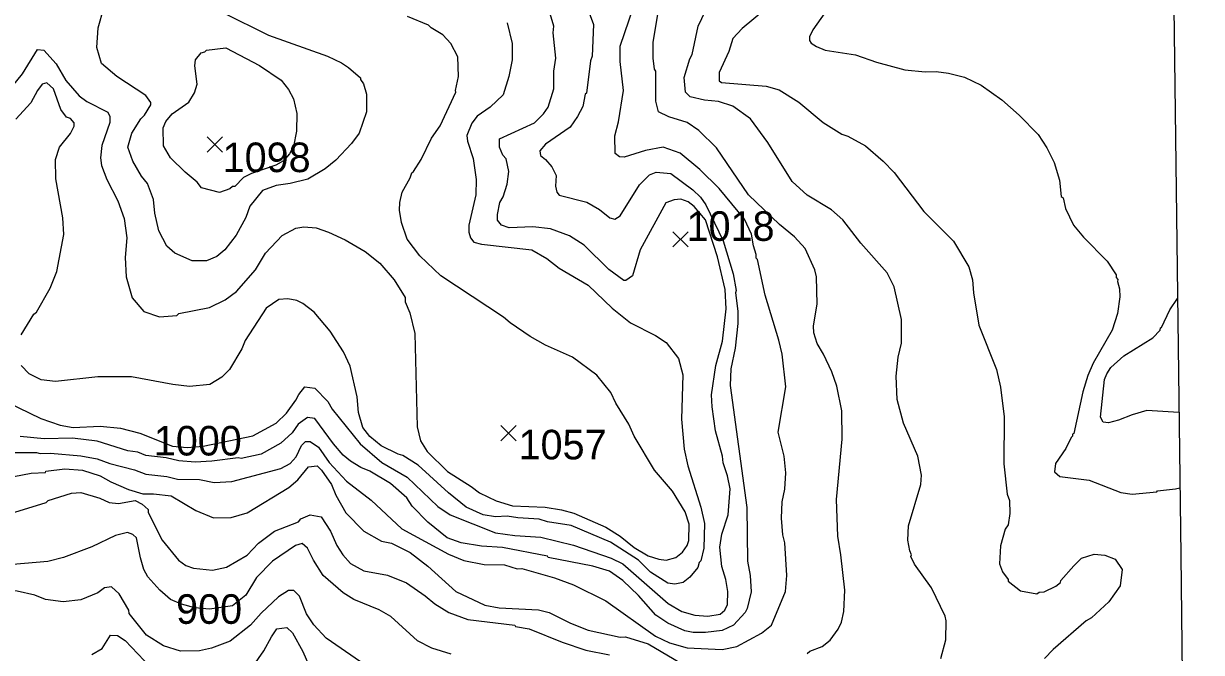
# Model space of a CAD drawing. Extents: x 265.7 to 292.1, y 7676.2 to 7704.2.
# Drawn here: x 288.719 to 291.905, y 7696.597 to 7698.298 of the extents above; entities that cross this region are included whole.
import ezdxf
from ezdxf.enums import TextEntityAlignment as Align

# ---------------------------------------------------------------- set-up
doc = ezdxf.new("R2010")
doc.units = 0
doc.header["$LTSCALE"] = 0.032
for name, color, linetype, lineweight in [('1', 7, 'Continuous', 25), ('2', 7, 'Continuous', 13), ('21', 7, 'Continuous', 25), ('63', 7, 'Continuous', 25)]:
    doc.layers.add(name, color=color, linetype=linetype, lineweight=lineweight)
doc.layers.add('61', color=7, linetype='Continuous')

msp = doc.modelspace()

# ---------------------------------------------------------------- linework, layer by layer
at = {"layer": '1'}
for points in [[(289.5532, 7697.2552), (289.629, 7697.1611), (289.688, 7697.1108), (289.7559, 7697.0709), (289.8396, 7696.9919), (289.8724, 7696.9696), (289.9953, 7696.9209), (290.0479, 7696.9129), (290.1181, 7696.9089), (290.2059, 7696.8874), (290.3081, 7696.8515), (290.34, 7696.8363), (290.4621, 7696.7294), (290.4996, 7696.7078), (290.5347, 7696.6975), (290.5698, 7696.6951), (290.6033, 7696.7006), (290.6153, 7696.711), (290.6224, 7696.727), (290.624, 7696.7621), (290.6185, 7696.794), (290.6073, 7696.8291), (290.6017, 7696.8818), (290.6073, 7696.9169), (290.6248, 7696.9696), (290.6296, 7697.0398), (290.6232, 7697.0749), (290.6113, 7697.11), (290.6097, 7697.1276), (290.5905, 7697.1962), (290.581, 7697.2616), (290.5794, 7697.2935), (290.5913, 7697.3733), (290.6089, 7697.4388), (290.6193, 7697.5265), (290.6161, 7697.5792), (290.5953, 7697.667), (290.563, 7697.7675), (290.5328, 7697.8033), (290.5163, 7697.8162), (290.4964, 7697.8234), (290.4788, 7697.821), (290.4557, 7697.813), (290.3862, 7697.6861), (290.3655, 7697.6159), (290.348, 7697.6031), (290.3424, 7697.6031), (290.3017, 7697.6327), (290.2354, 7697.6989), (290.1955, 7697.7236), (290.1437, 7697.7428), (290.0958, 7697.7484), (290.032, 7697.746), (290.0112, 7697.7532), (290.0008, 7697.7667), (290.0008, 7697.7819), (290.0072, 7697.8138), (290.016, 7697.8298), (290.0264, 7697.8633), (290.0312, 7697.8984), (290.024, 7697.9319), (290.0152, 7697.9423), (290.0056, 7697.9638), (290.0056, 7697.9862), (290.1006, 7698.0292), (290.1253, 7698.054), (290.1373, 7698.0724), (290.1532, 7698.1218), (290.1532, 7698.1697), (290.158, 7698.2048), (290.1516, 7698.2734), (290.1532, 7698.291), (290.1381, 7698.3421)], [(290.7254, 7698.3373), (290.6624, 7698.2846), (290.6368, 7698.2575), (290.6264, 7698.2224), (290.6001, 7698.1657), (290.6001, 7698.1434), (290.6065, 7698.1386), (290.7278, 7698.129), (290.7629, 7698.1186), (290.8156, 7698.0859), (290.8818, 7698.0301)], [(290.8818, 7698.0301), (290.9321, 7697.9989), (290.948, 7697.9933), (290.9959, 7697.967), (291.0438, 7697.9255), (291.0733, 7697.8952), (291.1539, 7697.7899)], [(291.1539, 7697.7899), (291.2345, 7697.7093), (291.2752, 7697.6399), (291.2856, 7697.6047), (291.2879, 7697.5696), (291.3023, 7697.4819), (291.3502, 7697.3622), (291.3614, 7697.3143), (291.3709, 7697.2345), (291.3701, 7697.1068), (291.3789, 7697.0254), (291.3853, 7697.0079), (291.3869, 7696.9728), (291.3821, 7696.9424), (291.3741, 7696.9305), (291.3614, 7696.885), (291.3582, 7696.8363), (291.3669, 7696.8148), (291.3821, 7696.794), (291.3821, 7696.79), (291.4156, 7696.7637), (291.4595, 7696.7557), (291.4659, 7696.7597), (291.4795, 7696.7613), (291.5114, 7696.7764), (291.5233, 7696.786), (291.5249, 7696.7916), (291.5593, 7696.8315), (291.5808, 7696.8515), (291.6151, 7696.8626), (291.6438, 7696.8602), (291.6718, 7696.8491), (291.6901, 7696.8212), (291.6853, 7696.7772), (291.6542, 7696.7342), (291.6079, 7696.6903), (291.5928, 7696.6823), (291.5034, 7696.6049), (291.4803, 7696.5809)], [(289.4295, 7697.2441), (289.455, 7697.2792), (289.463, 7697.2951), (289.4798, 7697.3151), (289.5069, 7697.3119), (289.5412, 7697.276), (289.5532, 7697.2552)], [(288.6419, 7697.2895), (288.7648, 7697.2297), (288.8175, 7697.2121), (288.8526, 7697.2058), (288.926, 7697.2089), (288.9803, 7697.2034), (289.0329, 7697.1898), (289.1217, 7697.155), (289.1613, 7697.1513), (289.2046, 7697.155), (289.3384, 7697.1833), (289.4016, 7697.2169), (289.4295, 7697.2441)], [(289.0872, 7696.7653), (289.0544, 7696.8012), (289.0441, 7696.8212), (289.0345, 7696.8531), (289.0241, 7696.9065), (289.0145, 7696.9161), (288.9994, 7696.9217), (288.9675, 7696.9129), (288.9036, 7696.8826), (288.827, 7696.8539), (288.784, 7696.8427), (288.6898, 7696.8347)], [(289.8756, 7696.5921), (289.8229, 7696.6089), (289.7846, 7696.628), (289.712, 7696.6943), (289.6801, 7696.7126), (289.6122, 7696.7405), (289.5827, 7696.7581), (289.5292, 7696.8052), (289.5029, 7696.8467), (289.4869, 7696.8786), (289.4718, 7696.8914), (289.4542, 7696.8858), (289.392, 7696.8435), (289.3489, 7696.7996), (289.3194, 7696.7517)], [(289.3194, 7696.7517), (289.2836, 7696.7233), (289.2214, 7696.7139), (289.1818, 7696.7177), (289.146, 7696.7271), (289.1159, 7696.7403), (289.0872, 7696.7653)]]:
    msp.add_lwpolyline(points, dxfattribs=at)
at = {"layer": '2'}
for points in [[(290.8379, 7696.5937), (290.8451, 7696.6001), (290.8786, 7696.6129), (290.9009, 7696.6304), (290.9225, 7696.66), (290.9313, 7696.6791), (290.9376, 7696.7078), (290.94, 7696.7653), (290.9297, 7696.861), (290.9209, 7696.9113), (290.9177, 7697.0111), (290.9329, 7697.1738), (290.9321, 7697.2505), (290.9185, 7697.3175), (290.9049, 7697.3558), (290.8826, 7697.4037), (290.865, 7697.4324), (290.8563, 7697.4611), (290.8555, 7697.4803), (290.865, 7697.5393), (290.8634, 7697.6127), (290.8586, 7697.6319), (290.8331, 7697.6893), (290.8044, 7697.7212), (290.7637, 7697.7548), (290.6799, 7697.8346), (290.5929, 7697.9622), (290.5451, 7698.0085), (290.5139, 7698.0301), (290.4645, 7698.046), (290.4365, 7698.0596), (290.4293, 7698.0883), (290.4293, 7698.1697), (290.4254, 7698.1745), (290.4214, 7698.2048), (290.4214, 7698.2479), (290.4453, 7698.3883)], [(291.2002, 7696.5802), (291.2137, 7696.6312), (291.2145, 7696.6823), (291.2113, 7696.6951), (291.1746, 7696.7717), (291.1284, 7696.8355), (291.1188, 7696.8563), (291.1204, 7696.861), (291.1156, 7696.8722), (291.1108, 7696.9009), (291.1124, 7696.9392), (291.1459, 7697.051), (291.1475, 7697.0765), (291.1379, 7697.1276), (291.0988, 7697.2169), (291.0821, 7697.2808), (291.0789, 7697.3446), (291.0845, 7697.3957), (291.0932, 7697.434), (291.0932, 7697.4978), (291.0741, 7697.5856), (291.0549, 7697.6239), (290.9839, 7697.7037), (290.9345, 7697.7675), (290.9041, 7697.7939), (290.8379, 7697.8338), (290.798, 7697.8713), (290.7318, 7697.9766), (290.6847, 7698.0404), (290.6368, 7698.0747), (290.5985, 7698.0875), (290.5602, 7698.0907), (290.5219, 7698.1003), (290.5091, 7698.113), (290.5059, 7698.1522), (290.5211, 7698.2032), (290.5275, 7698.2144), (290.5435, 7698.291), (290.5937, 7698.3971)], [(290.9081, 7698.358), (290.8539, 7698.2814), (290.8443, 7698.2623), (290.8443, 7698.2527), (290.8491, 7698.2455), (290.8634, 7698.2359), (290.8874, 7698.2264), (290.9688, 7698.2136), (291.0262, 7698.1936), (291.1028, 7698.1729), (291.1571, 7698.1673), (291.1874, 7698.1689), (291.2209, 7698.1641), (291.264, 7698.1529), (291.3087, 7698.1314)], [(288.1129, 7698.3165), (288.1153, 7698.2527), (288.1129, 7698.1761), (288.1177, 7698.0899), (288.1264, 7698.0396), (288.1328, 7698.0332), (288.1392, 7698.0005), (288.1671, 7697.9463), (288.2126, 7697.9048), (288.2876, 7697.8784), (288.3195, 7697.88), (288.4313, 7697.9231), (288.4759, 7697.9447), (288.515, 7697.971), (288.5717, 7698.0157), (288.6882, 7698.129), (288.7153, 7698.1625), (288.756, 7698.228), (288.7736, 7698.2264), (288.8071, 7698.1889), (288.8326, 7698.1442), (288.8685, 7698.1027), (288.8893, 7698.0875), (288.9467, 7698.0588)], [(289.2579, 7698.3285), (289.3808, 7698.267), (289.5404, 7698.2104), (289.5787, 7698.192), (289.5979, 7698.1793), (289.6298, 7698.1514), (289.6298, 7698.1466), (289.6378, 7698.1354), (289.6465, 7698.1075), (289.6465, 7698.0596), (289.6266, 7698.0021), (289.6058, 7697.9734), (289.5636, 7697.9287), (289.534, 7697.9056), (289.4878, 7697.8776), (289.4399, 7697.8657), (289.4016, 7697.8601), (289.3649, 7697.8465), (289.3306, 7697.8042), (289.3202, 7697.7739), (289.2938, 7697.726), (289.2627, 7697.6861), (289.2412, 7697.6678), (289.2133, 7697.6566), (289.175, 7697.6566), (289.1279, 7697.6766), (289.1063, 7697.6957), (289.0848, 7697.7372), (289.0736, 7697.7851), (289.0704, 7697.8226), (289.0537, 7697.8657), (289.0377, 7697.8856), (289.0138, 7697.9255), (289.0002, 7697.9638), (289.0114, 7698.0021), (289.0361, 7698.0404), (289.0457, 7698.05), (289.0624, 7698.0787), (289.0624, 7698.0843), (289.0497, 7698.1035), (288.9707, 7698.1553), (288.9292, 7698.1904), (288.9164, 7698.2335), (288.9204, 7698.2862), (288.9356, 7698.3405)], [(288.9435, 7697.8761), (288.9739, 7697.8186), (288.9906, 7697.7707), (288.9978, 7697.7181), (288.9938, 7697.6654), (288.9962, 7697.6127), (289.0122, 7697.5561), (289.0441, 7697.5194), (289.0864, 7697.505), (289.1327, 7697.5082), (289.139, 7697.5138), (289.2212, 7697.5305), (289.2643, 7697.5505), (289.2947, 7697.5736), (289.3457, 7697.6319), (289.3728, 7697.6766), (289.4183, 7697.7252), (289.455, 7697.7444), (289.4766, 7697.7484), (289.5101, 7697.7452), (289.5436, 7697.734), (289.5883, 7697.7133), (289.6426, 7697.6813), (289.6825, 7697.6502), (289.7215, 7697.6047), (289.7511, 7697.5569), (289.7511, 7697.5457), (289.7638, 7697.5154), (289.7766, 7697.4595), (289.783, 7697.2074), (289.7926, 7697.1691), (289.8101, 7697.1403), (289.8652, 7697.0861), (289.9298, 7697.0462), (289.9522, 7697.0286), (289.9969, 7697.0071), (290.0415, 7696.9935), (290.1293, 7696.9895), (290.174, 7696.9831), (290.2075, 7696.9736), (290.2937, 7696.936), (290.332, 7696.9113), (290.3703, 7696.881), (290.4086, 7696.8586), (290.4373, 7696.8491), (290.4565, 7696.8467), (290.4828, 7696.8539), (290.5012, 7696.8682), (290.5139, 7696.8858), (290.5179, 7696.8994), (290.5195, 7696.944), (290.5083, 7696.9776), (290.474, 7697.0334), (290.4254, 7697.0901), (290.3703, 7697.1818), (290.3559, 7697.2145), (290.3208, 7697.2712), (290.3073, 7697.2999), (290.269, 7697.347), (290.2035, 7697.3957), (290.1309, 7697.4284), (290.0894, 7697.4515), (290.0352, 7697.4882), (290.0168, 7697.5042), (289.8476, 7697.6159), (289.7902, 7697.6702), (289.7559, 7697.7149), (289.7407, 7697.7596), (289.7359, 7697.7931), (289.7367, 7697.8138), (289.7431, 7697.8425), (289.7646, 7697.8808), (289.7686, 7697.8944), (289.7734, 7697.8976), (289.7942, 7697.9303), (289.8221, 7697.9878), (289.8452, 7698.0213), (289.8883, 7698.113), (289.8867, 7698.117), (289.8947, 7698.1553), (289.8931, 7698.208), (289.8748, 7698.2447), (289.8524, 7698.2679), (289.8213, 7698.2862), (289.8141, 7698.2934), (289.7575, 7698.3173)], [(290.0192, 7696.8339), (290.0535, 7696.8235), (290.0663, 7696.8243), (290.1548, 7696.7988), (290.2059, 7696.7796), (290.2937, 7696.7366), (290.4278, 7696.6408), (290.4661, 7696.6225), (290.5139, 7696.6097), (290.6081, 7696.6049), (290.648, 7696.6129), (290.715, 7696.6488), (290.7421, 7696.6711), (290.7797, 7696.7621), (290.7836, 7696.8052), (290.7781, 7696.893), (290.7725, 7696.9153), (290.7693, 7696.96), (290.7709, 7697.0047), (290.7781, 7697.0382), (290.7804, 7697.0829), (290.7765, 7697.1276), (290.7597, 7697.193), (290.7805, 7697.3151), (290.7709, 7697.4037), (290.7621, 7697.442), (290.7246, 7697.5633), (290.7038, 7697.6598), (290.7007, 7697.6638), (290.7007, 7697.6734), (290.6927, 7697.6973), (290.6879, 7697.7281), (290.6691, 7697.769), (290.6001, 7697.8521), (290.5482, 7697.9032), (290.4948, 7697.9479), (290.4485, 7697.9638), (290.4006, 7697.955), (290.3432, 7697.9367), (290.3304, 7697.9375), (290.3192, 7697.9471), (290.3176, 7697.9949), (290.328, 7698.0325), (290.3416, 7698.117), (290.3328, 7698.1952), (290.3328, 7698.2367), (290.3687, 7698.3421)], [(290.2458, 7698.3341), (290.2602, 7698.2958), (290.257, 7698.2096), (290.2522, 7698.1976), (290.241, 7698.1099), (290.2378, 7698.1075), (290.2314, 7698.0739), (290.2171, 7698.0468), (290.1971, 7698.0181), (290.1309, 7697.9718), (290.115, 7697.9542), (290.1165, 7697.9415), (290.1309, 7697.9303), (290.1477, 7697.9104), (290.1596, 7697.8872), (290.1572, 7697.8585), (290.1612, 7697.8417), (290.1676, 7697.8338), (290.2426, 7697.8146), (290.2761, 7697.7955), (290.3049, 7697.7723), (290.3184, 7697.7691), (290.3328, 7697.7779), (290.3847, 7697.8617), (290.4118, 7697.8888), (290.4301, 7697.896), (290.4693, 7697.8928), (290.5291, 7697.8481), (290.5498, 7697.8282)], [(290.0272, 7698.3006), (290.0399, 7698.2447), (290.0407, 7698.2), (290.0312, 7698.1553), (290.016, 7698.1051), (289.9809, 7698.0723), (289.9458, 7698.0476), (289.9314, 7698.0285), (289.9179, 7697.9957), (289.9194, 7697.9798), (289.9346, 7697.9335), (289.9426, 7697.8761), (289.9418, 7697.8346), (289.9234, 7697.7532), (289.9234, 7697.734)], [(288.7121, 7697.4563), (288.7464, 7697.5122), (288.7536, 7697.517), (288.7903, 7697.5824), (288.8087, 7697.6271), (288.8278, 7697.7276), (288.8246, 7697.7723), (288.8055, 7697.8777), (288.8047, 7697.9303), (288.8159, 7697.9638), (288.8454, 7698.0005), (288.8558, 7698.0205), (288.8558, 7698.0293), (288.8454, 7698.0412), (288.835, 7698.0452), (288.8191, 7698.066), (288.7991, 7698.1218), (288.7816, 7698.1378), (288.7688, 7698.1346), (288.756, 7698.117), (288.7385, 7698.0835), (288.6978, 7698.0396)], [(291.3087, 7698.1314), (291.3646, 7698.0923), (291.4116, 7698.0508), (291.4635, 7697.9981), (291.4866, 7697.9622), (291.5066, 7697.9223), (291.521, 7697.8745)], [(288.9467, 7698.0588), (288.9515, 7698.0468), (288.9515, 7698.0301), (288.93, 7697.9686), (288.9268, 7697.9351), (288.9292, 7697.9144), (288.9435, 7697.8761)], [(291.521, 7697.8745), (291.5257, 7697.8306), (291.5305, 7697.8266), (291.5369, 7697.7979), (291.5585, 7697.7532), (291.5856, 7697.7205), (291.6502, 7697.6558), (291.6742, 7697.6183), (291.6742, 7697.6111), (291.679, 7697.6055), (291.6774, 7697.6), (291.6829, 7697.5808), (291.6845, 7697.5585), (291.6782, 7697.5138), (291.663, 7697.4691), (291.6119, 7697.3797), (291.5976, 7697.3462), (291.584, 7697.3015), (291.5593, 7697.189), (291.5561, 7697.1874), (291.5561, 7697.1818), (291.5521, 7697.1786), (291.5385, 7697.1483), (291.5098, 7697.1076), (291.5074, 7697.0853), (291.5218, 7697.0725), (291.6008, 7697.0629), (291.6869, 7697.0294), (291.7173, 7697.0254), (291.7843, 7697.031), (291.7859, 7697.0342), (291.8346, 7697.0398), (291.8465, 7697.0423)], [(290.5498, 7697.8282), (290.5642, 7697.8074), (290.6115, 7697.7106), (290.6384, 7697.6207), (290.6464, 7697.576), (290.6448, 7697.5696), (290.6504, 7697.5202)], [(289.9234, 7697.734), (289.9274, 7697.7189), (289.937, 7697.7069), (289.957, 7697.7013), (290.0934, 7697.6861), (290.1341, 7697.663), (290.1676, 7697.6367)], [(290.1676, 7697.6367), (290.2458, 7697.5904), (290.3112, 7697.5281), (290.3607, 7697.489), (290.4278, 7697.4547), (290.4565, 7697.4356), (290.49, 7697.3925), (290.502, 7697.3478), (290.498, 7697.2281), (290.5059, 7697.1467), (290.5155, 7697.102), (290.5506, 7696.9903), (290.5602, 7696.9456), (290.5586, 7696.8786), (290.5506, 7696.8451), (290.5458, 7696.8403), (290.5427, 7696.8267), (290.5211, 7696.8004), (290.5028, 7696.786), (290.4804, 7696.7812), (290.4613, 7696.7844), (290.4142, 7696.814), (290.3823, 7696.8467), (290.3065, 7696.8954), (290.1995, 7696.94), (290.1357, 7696.9504), (290.1134, 7696.9576), (290.0559, 7696.9608), (290.0272, 7696.9656), (289.9953, 7696.964), (289.9617, 7696.9688), (289.9155, 7696.9903), (289.8684, 7697.0286), (289.7862, 7697.1036), (289.7447, 7697.13), (289.7319, 7697.1331), (289.6857, 7697.1555), (289.6553, 7697.181), (289.6362, 7697.2058), (289.625, 7697.2457), (289.621, 7697.2888), (289.6019, 7697.3717), (289.5843, 7697.41), (289.5476, 7697.4659), (289.5045, 7697.517), (289.4742, 7697.5409), (289.4582, 7697.5489), (289.4335, 7697.5537), (289.4088, 7697.5521), (289.3744, 7697.5281), (289.3178, 7697.4404), (289.309, 7697.418), (289.2755, 7697.3622), (289.2547, 7697.3414), (289.2228, 7697.3215), (289.1678, 7697.3167), (289.1223, 7697.3215), (289.0106, 7697.3422), (288.9196, 7697.3422), (288.8047, 7697.3302), (288.7664, 7697.3342), (288.7337, 7697.351), (288.7121, 7697.3733)], [(291.844, 7697.246), (291.7572, 7697.2512), (291.7173, 7697.2401), (291.6806, 7697.2249), (291.6534, 7697.2185), (291.6391, 7697.2201), (291.6319, 7697.2337), (291.643, 7697.335), (291.6486, 7697.351), (291.6598, 7697.3677), (291.6949, 7697.3989), (291.7731, 7697.4483), (291.7931, 7697.4683), (291.7939, 7697.4747), (291.7971, 7697.4763), (291.8194, 7697.5234), (291.8401, 7697.5545)], [(290.6504, 7697.5202), (290.6504, 7697.4867), (290.6432, 7697.4196), (290.632, 7697.3638), (290.6304, 7697.3191), (290.6751, 7696.9887), (290.6767, 7696.8435), (290.6839, 7696.8052), (290.6871, 7696.7605), (290.6759, 7696.7158), (290.6703, 7696.7046), (290.6392, 7696.6703), (290.6081, 7696.656), (290.5634, 7696.6504), (290.5299, 7696.6512), (290.5076, 7696.6552), (290.4613, 7696.6759), (290.4285, 7696.6975), (290.3823, 7696.7509), (290.34, 7696.7916), (290.3033, 7696.8164), (290.2586, 7696.8307), (290.1373, 7696.8539), (290.1357, 7696.8571), (290.0144, 7696.881), (289.957, 7696.8842), (289.9027, 7696.8938), (289.8644, 7696.9073), (289.8125, 7696.9496), (289.7702, 7696.9927), (289.7551, 7697.0151), (289.7112, 7697.0541), (289.6553, 7697.0869), (289.6306, 7697.0972), (289.6027, 7697.114), (289.5835, 7697.1308), (289.5572, 7697.1611), (289.5069, 7697.2297), (289.4862, 7697.2329), (289.4614, 7697.2145), (289.4455, 7697.1914), (289.4143, 7697.1627), (289.3617, 7697.1331), (289.3074, 7697.122), (289.2994, 7697.1236), (289.2276, 7697.114), (289.1829, 7697.1116), (289.1383, 7697.1156), (289.1047, 7697.1236), (289.0489, 7697.13), (289.0273, 7697.1387), (289.001, 7697.1427), (288.918, 7697.1683), (288.851, 7697.1762), (288.7744, 7697.1746), (288.7089, 7697.181)], [(288.6802, 7697.1379), (288.7536, 7697.1379), (288.7632, 7697.1347), (288.7911, 7697.1363), (288.8733, 7697.1284), (288.918, 7697.1204), (288.9515, 7697.1084), (289.0186, 7697.0909), (289.0489, 7697.0789), (289.1063, 7697.0725), (289.1351, 7697.0661), (289.1941, 7697.0645), (289.234, 7697.0565), (289.2819, 7697.0589), (289.4143, 7697.0948), (289.4399, 7697.1084), (289.4558, 7697.126), (289.4702, 7697.1563), (289.4814, 7697.1675), (289.4941, 7697.1675), (289.5165, 7697.1523), (289.5452, 7697.1108), (289.5923, 7697.0605)], [(288.7792, 7697.0869), (288.8302, 7697.094), (288.8781, 7697.0901), (288.926, 7697.0749), (288.9547, 7697.0581), (289.0026, 7697.0374), (289.0409, 7697.0262), (289.0696, 7697.0262), (289.1175, 7697.0206), (289.1845, 7696.9807), (289.2324, 7696.9608), (289.2803, 7696.9624), (289.3234, 7696.9743), (289.4359, 7697.043), (289.4606, 7697.0637), (289.4893, 7697.0988), (289.5125, 7697.102), (289.5245, 7697.0901), (289.5516, 7697.051), (289.5636, 7697.0222), (289.5899, 7696.9744), (289.6394, 7696.9249), (289.6872, 7696.8977), (289.7136, 7696.8922), (289.7639, 7696.8674), (289.8117, 7696.8307), (289.8883, 7696.7621), (289.9665, 7696.7246), (290.0048, 7696.7174), (290.1118, 7696.7118), (290.1405, 7696.7046), (290.1979, 7696.6759), (290.2458, 7696.6568), (290.332, 7696.6384), (290.3472, 7696.6392), (290.4086, 7696.6201), (290.5139, 7696.5578)], [(288.6443, 7697.0581), (288.6451, 7697.0613), (288.6834, 7697.0685), (288.6922, 7697.0733), (288.7393, 7697.0821), (288.7776, 7697.0837), (288.7792, 7697.0869)], [(289.5923, 7697.0605), (289.6585, 7697.0087), (289.7415, 7696.9313), (289.8676, 7696.8626), (289.9091, 7696.8459), (289.9649, 7696.8347), (290.0192, 7696.8339)], [(288.6946, 7696.9767), (288.78, 7697.0023), (288.7847, 7697.0079), (288.8478, 7697.0278), (288.8733, 7697.0294), (288.9244, 7697.0142), (288.9499, 7697.0023), (288.9755, 7696.9999), (289.0201, 7697.0079), (289.0393, 7696.9983), (289.0553, 7696.9839), (289.056, 7696.9759), (289.0936, 7696.9009), (289.1374, 7696.8467), (289.1574, 7696.8323), (289.1781, 7696.8251), (289.2292, 7696.8195), (289.2675, 7696.8275), (289.3234, 7696.8602), (289.3537, 7696.8922), (289.3976, 7696.9249), (289.4622, 7696.9504), (289.4686, 7696.9584), (289.4941, 7696.9688), (289.5237, 7696.964)], [(289.5237, 7696.964), (289.5484, 7696.9249), (289.5659, 7696.8866), (289.5819, 7696.861), (289.6027, 7696.8379), (289.6394, 7696.818), (289.7032, 7696.806)], [(289.7032, 7696.806), (289.7543, 7696.7852), (289.8053, 7696.7501), (289.8309, 7696.7286), (289.8692, 7696.7046), (289.9203, 7696.6863), (290.0479, 7696.6703), (290.0495, 7696.6671), (290.0862, 7696.6608), (290.1756, 7696.6248), (290.2394, 7696.6033), (290.3033, 7696.5905)], [(288.8733, 7696.739), (288.8254, 7696.7334), (288.7776, 7696.7405), (288.7488, 7696.7517), (288.701, 7696.7629), (288.677, 7696.7645), (288.6698, 7696.7581)], [(289.6298, 7696.5714), (289.5372, 7696.6352), (289.5037, 7696.6719), (289.4838, 7696.7015), (289.4646, 7696.7493), (289.4495, 7696.7645), (289.4351, 7696.7645), (289.408, 7696.7477), (289.3609, 7696.703), (289.3321, 7696.6703), (289.2771, 7696.6272), (289.2268, 7696.6081), (289.1941, 7696.6017), (289.143, 7696.6001), (289.0975, 7696.6145), (289.0513, 7696.6432), (289.0042, 7696.7023), (289.0034, 7696.711), (288.9771, 7696.7557), (288.9563, 7696.7741), (288.9372, 7696.7717), (288.9196, 7696.7581), (288.8733, 7696.739)], [(289.3314, 7696.5482), (289.3689, 7696.6009), (289.3888, 7696.6392), (289.404, 7696.6608), (289.4311, 7696.6647), (289.4463, 7696.6496), (289.4742, 7696.5993), (289.4949, 7696.5514)], [(288.9028, 7696.5913), (288.9308, 7696.6073), (288.9539, 7696.6432), (288.9723, 7696.6424), (288.993, 7696.6296), (289.0616, 7696.557)]]:
    msp.add_lwpolyline(points, dxfattribs=at)
msp.add_lwpolyline([(289.457, 7698.0073), (289.4486, 7697.9659), (289.4378, 7697.9459), (289.4219, 7697.9266), (289.4009, 7697.9149), (289.3348, 7697.8923), (289.3131, 7697.8814), (289.2899, 7697.8577), (289.2835, 7697.8577), (289.2763, 7697.8513), (289.2484, 7697.8409), (289.1997, 7697.8537), (289.1885, 7697.8689), (289.1558, 7697.896), (289.1159, 7697.9351), (289.0975, 7697.967), (289.096, 7698.0165), (289.1031, 7698.0332), (289.1207, 7698.054), (289.1654, 7698.0859), (289.1813, 7698.1107), (289.1885, 7698.1346), (289.1821, 7698.1841), (289.1837, 7698.2), (289.1989, 7698.2192), (289.2085, 7698.2216), (289.2133, 7698.2264), (289.2659, 7698.2327), (289.3569, 7698.1849), (289.4151, 7698.145), (289.4351, 7698.1202), (289.4487, 7698.0947), (289.4582, 7698.0548)], close=True, dxfattribs=at)
at = {"layer": '21'}
for p, q in [((289.2154, 7697.9917), (289.2566, 7697.9505)), ((289.2566, 7697.9917), (289.2154, 7697.9505)), ((290.4752, 7697.7352), (290.5164, 7697.694)), ((290.5164, 7697.7352), (290.4752, 7697.694)), ((290.0095, 7697.2105), (290.0507, 7697.1693)), ((290.0507, 7697.2105), (290.0095, 7697.1693))]:
    msp.add_line(p, q, dxfattribs=at)
at = {"layer": '63', "lineweight": 13}
msp.add_lwpolyline([(291.7577, 7704.203), (291.7647, 7703.638), (291.7717, 7703.0731), (291.7787, 7702.5082), (291.7857, 7701.9433), (291.7927, 7701.3784), (291.7997, 7700.8135), (291.8067, 7700.2486), (291.8137, 7699.6837), (291.8207, 7699.1188), (291.8277, 7698.5539), (291.8347, 7697.9889), (291.8417, 7697.424), (291.8487, 7696.8591), (291.8557, 7696.2942), (291.8628, 7695.7293), (291.8698, 7695.1644), (291.8768, 7694.5995), (291.8838, 7694.0345), (291.8908, 7693.4696), (291.8978, 7692.9047), (291.9049, 7692.3398)], dxfattribs=at)

# ---------------------------------------------------------------- texts
at = {"layer": '61'}
for s, p in [('1098', (289.3761, 7697.8963)), ('1018', (290.6311, 7697.7103)), ('1000', (289.1898, 7697.1297)), ('1057', (290.1766, 7697.1192)), ('900', (289.2205, 7696.6743))]:
    msp.add_text(s, height=0.08, dxfattribs=at).set_placement(p, align=Align.CENTER)

doc.saveas('drawing.dxf')
